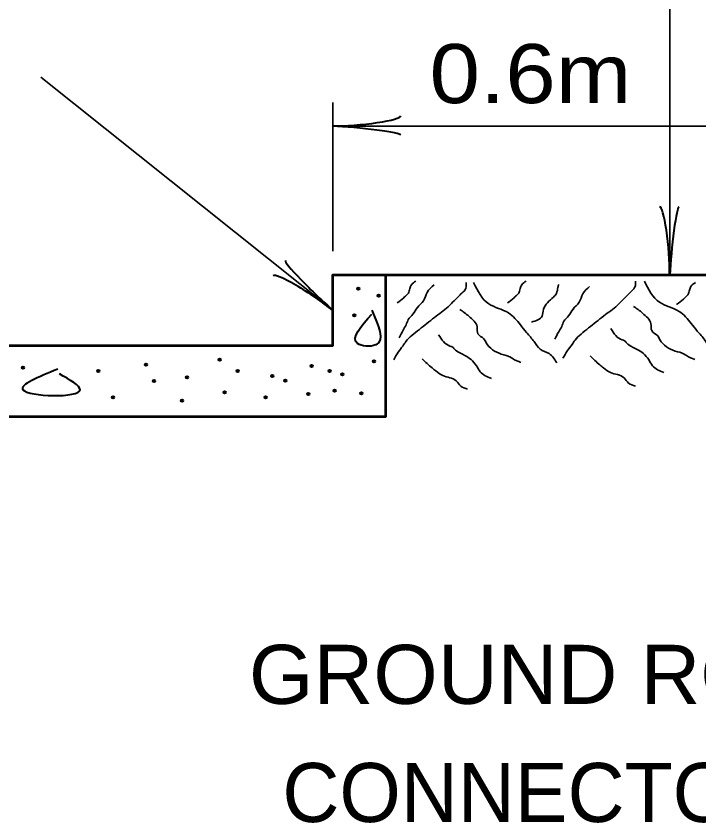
# Model space of a CAD drawing. Extents: x 14808 to 15663, y 10944 to 11488.
# Drawn here: x 15128.3 to 15162.98, y 11248.79 to 11289.76 of the extents above; entities that cross this region are included whole.
import ezdxf
from ezdxf.enums import TextEntityAlignment as Align

# ---------------------------------------------------------------- set-up
doc = ezdxf.new("R2010")
doc.units = 0
doc.header["$LTSCALE"] = 1.2
doc.layers.add('1', color=7, linetype='Continuous', lineweight=53)

msp = doc.modelspace()

# ---------------------------------------------------------------- linework, layer by layer
at = {"layer": '1', "lineweight": 35}
for p, q in [((15144.385, 11274.824), (15129.548, 11286.654)), ((15144.385, 11277.824), (15144.385, 11285.375)), ((15144.385, 11284.175), (15180.817, 11284.175))]:
    msp.add_line(p, q, dxfattribs=at)
msp.add_lwpolyline([(15161.508, 11339.136), (15161.508, 11321.136), (15161.508, 11276.623)], dxfattribs=at)
at = {"layer": '1'}
for points in [[(14994.385, 11273.024), (15144.385, 11273.024), (15144.385, 11276.623), (15179.229, 11276.623)], [(14994.385, 11273.001), (14994.385, 11269.424), (15147.085, 11269.424), (15147.085, 11276.623)]]:
    msp.add_lwpolyline(points, dxfattribs=at)
at = {"layer": '1', "lineweight": 40}
for centre in [(15145.678, 11275.918), (15146.724, 11275.563), (15145.474, 11274.563), (15138.641, 11272.314), (15146.474, 11272.23), (15128.643, 11271.897), (15134.888, 11272.053), (15143.308, 11271.981), (15132.472, 11271.731), (15136.981, 11271.409), (15139.558, 11271.731), (15141.307, 11271.481), (15144.224, 11271.731), (15144.873, 11271.57), (15135.309, 11271.231), (15141.974, 11271.247), (15138.891, 11270.648), (15143.141, 11270.564), (15144.474, 11270.731), (15145.84, 11270.603), (15133.226, 11270.398), (15136.725, 11270.231), (15140.975, 11270.398)]:
    msp.add_circle(centre, 0.06, dxfattribs=at)
for centre, major_axis, ratio, start_param, end_param in [((15145.695, 11284.507), (-2.143, -0.187), 0.122415, 0.896353, 3.141593), ((15145.695, 11284.507), (-2.143, -0.187), 0.122415, 0.896353, 3.141593), ((15145.73, 11283.921), (-2.108, 0.211), 0.07063, 3.140715, 5.41811), ((15145.73, 11283.921), (-2.108, 0.211), 0.07063, 3.140715, 5.41811), ((15161.177, 11277.933), (0.187, -2.143), 0.122415, 0.896353, 3.141593), ((15161.762, 11277.968), (0.211, 2.108), 0.07063, 6.282307, 8.559703), ((15143.492, 11275.86), (1.517, -1.479), 0.07063, 3.140715, 5.41811), ((15143.155, 11275.381), (1.792, -1.189), 0.122415, 0.896353, 3.141593)]:
    msp.add_ellipse(centre, major_axis=major_axis, ratio=ratio, start_param=start_param, end_param=end_param, dxfattribs=at)
at = {"layer": '1', "lineweight": 35}
for points in [[(15151.166, 11276.223), (15151.166, 11276.07), (15151.089, 11275.839), (15150.936, 11275.686), (15150.782, 11275.532), (15150.475, 11275.225), (15150.245, 11274.995), (15149.553, 11274.457), (15149.17, 11274.15), (15148.402, 11273.536), (15148.095, 11273.229), (15147.941, 11272.999), (15147.711, 11272.692), (15147.481, 11272.308)], [(15148.609, 11276.302), (15148.379, 11276.111), (15148.302, 11275.919), (15148.225, 11275.688), (15148.072, 11275.535), (15147.995, 11275.458), (15147.649, 11275.189)], [(15149.528, 11276.111), (15149.183, 11275.727), (15148.991, 11275.305), (15148.684, 11274.959), (15148.453, 11274.614), (15148.223, 11274.345), (15148.108, 11274.076), (15147.954, 11273.807), (15147.762, 11273.424)], [(15151.54, 11276.223), (15152.307, 11275.148), (15153.305, 11274.688), (15153.919, 11274.073), (15154.227, 11273.69), (15154.611, 11273.229), (15154.918, 11272.845), (15155.378, 11272.615), (15155.762, 11272.154)], [(15154.213, 11276.302), (15153.983, 11276.11), (15153.906, 11275.918), (15153.83, 11275.688), (15153.676, 11275.535), (15153.599, 11275.458), (15153.254, 11275.189)], [(15154.481, 11274.217), (15155.018, 11274.524), (15155.095, 11274.87), (15155.594, 11275.484), (15155.747, 11275.676), (15155.824, 11275.983), (15155.863, 11276.136)], [(15157.436, 11276.034), (15157.09, 11275.65), (15156.899, 11275.228), (15156.591, 11274.882), (15156.361, 11274.537), (15156.131, 11274.268), (15156.016, 11273.999), (15155.862, 11273.731), (15155.67, 11273.347)], [(15159.765, 11276.3), (15159.765, 11276.146), (15159.688, 11275.916), (15159.534, 11275.763), (15159.381, 11275.609), (15159.074, 11275.302), (15158.843, 11275.072), (15158.152, 11274.534), (15157.768, 11274.227), (15157.001, 11273.613), (15156.694, 11273.306), (15156.54, 11273.075), (15156.31, 11272.768), (15156.079, 11272.384)], [(15160.215, 11276.3), (15160.983, 11275.225), (15161.981, 11274.764), (15162.595, 11274.15), (15162.902, 11273.766), (15163.286, 11273.306), (15163.593, 11272.922), (15164.054, 11272.692), (15164.438, 11272.231)], [(15162.812, 11276.226), (15162.582, 11276.034), (15162.505, 11275.842), (15162.428, 11275.611), (15162.275, 11275.458), (15162.198, 11275.381), (15161.853, 11275.112)], [(15150.836, 11274.858), (15151.066, 11274.705), (15151.296, 11274.513), (15151.719, 11273.976), (15151.757, 11273.63), (15152.064, 11273.361), (15152.179, 11273.169), (15152.947, 11272.594), (15153.408, 11272.44), (15153.523, 11272.363), (15153.945, 11272.171)], [(15159.665, 11275.012), (15159.895, 11274.858), (15160.125, 11274.667), (15160.548, 11274.129), (15160.586, 11273.784), (15160.893, 11273.515), (15161.008, 11273.323), (15161.776, 11272.747), (15162.237, 11272.594), (15162.352, 11272.517), (15162.774, 11272.325)], [(15158.515, 11273.886), (15159.091, 11273.31), (15159.206, 11273.272), (15159.321, 11273.156), (15159.82, 11272.849), (15160.434, 11272.312), (15160.626, 11272.005), (15161.202, 11271.659)], [(15149.763, 11273.579), (15150.338, 11273.003), (15150.454, 11272.964), (15150.569, 11272.849), (15151.068, 11272.542), (15151.682, 11272.005), (15151.874, 11271.698), (15152.45, 11271.352)], [(15148.931, 11272.351), (15149.43, 11271.89), (15149.622, 11271.737), (15149.968, 11271.506), (15150.659, 11271.238), (15150.889, 11270.969), (15151.235, 11270.815)], [(15157.453, 11272.505), (15157.952, 11272.044), (15158.144, 11271.89), (15158.49, 11271.66), (15159.181, 11271.391), (15159.411, 11271.123), (15159.757, 11270.969)]]:
    msp.add_spline(points, degree=3, dxfattribs=at)
at = {"layer": '1', "lineweight": 40}
for points in [[(15146.363, 11274.83), (15146.564, 11273.059), (15145.638, 11273.139), (15146.363, 11274.629)], [(15130.418, 11271.831), (15128.647, 11270.784), (15131.546, 11270.784), (15130.499, 11271.589)]]:
    msp.add_spline(points, degree=3, dxfattribs=at)

# ---------------------------------------------------------------- texts
at = {"layer": '1'}
for s, width, p in [('0.6m', 1.15, (15154.429, 11285.34)), ('GROUND ROD', 1.05, (15154.751, 11254.828))]:
    msp.add_text(s, height=3, dxfattribs=dict(at, width=width)).set_placement(p, align=Align.CENTER)
msp.add_text('CONNECTOR', height=3, dxfattribs=at).set_placement((15154.751, 11248.828), align=Align.CENTER)

doc.saveas('drawing.dxf')
